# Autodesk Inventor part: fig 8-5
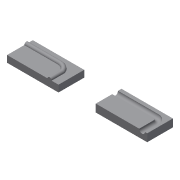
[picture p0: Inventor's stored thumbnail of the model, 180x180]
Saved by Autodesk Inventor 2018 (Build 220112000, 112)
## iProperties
Created: 2009-04
Part Number: fig 8-5
Document SubType Name: Modeling
Designer: Sham
Density: 1 g/cm^3
Material: Generic
Appearance: Default
Author: Sham
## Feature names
1. Extrusion1
2. Sweep5
3. Extrusion2
4. Sweep6
## Parameters: d0 = 6 mm, d1 = 0, d6 = 0, d7 = 5.25 mm, d8 = 0, d9 = 0, d10 = 0, d11 = 0
